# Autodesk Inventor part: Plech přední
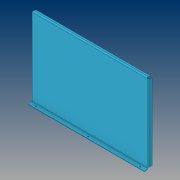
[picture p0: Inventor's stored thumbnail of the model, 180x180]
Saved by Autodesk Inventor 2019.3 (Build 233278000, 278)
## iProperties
Created: 2019-02
Part Number: Plech přední
Material: Ocel, měkká, svařovaná
Document SubType Name: Plech
Designer: B-hon
Density: 7.85 g/cm^3
Sheet Metal Rule: Výchozí_mm
Appearance: Tyrkysová
Flat Pattern Width: 51.832 cm
Flat Pattern Length: 74.7572 cm
Flat Pattern Area: 3874.81 cm^2
Sheet Metal Width: 518,320 mm
Sheet Metal Length: 747,572 mm
Sheet Metal Area: 387481,115 mm^2
Author: B-hon
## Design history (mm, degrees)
node "Plocha1"
  sketch "Náčrt1"
    geometry: L1 (-354, 235)-(354, 235); L2 (354, 235)-(354, -235); L3 (354, -235)-(-354, -235); L4 (-354, -235)-(-354, 235); L5 (-354, 235)-(354, -235); L6 (354, 235)-(-354, -235); 1 further point
    constraints: 12 end point, 2 midpoint, 2 parallel, 1 horizontal, 1 perpendicular
    dimensions: "d0" = 708 distance of L2.end L3.end; "d1" = 470 distance of L1.end L2.end
node "Obruba2"
node "Obruba7"
node "Upravit přímo6"
sketch "Náčrt11"
  geometry: L1 (9.039, 11.735)-(-3, 11.735); L2 (-3, 11.735)-(-3, -36.973); L3 (-3, -36.973)-(9.039, -36.973); L4 (9.039, -36.973)-(9.039, 11.735); L5 (-727.872, -54.321)-(-699, -54.321); L6 (-699, -54.321)-(-699, 24.046); L7 (-699, 24.046)-(-727.872, 24.046); L8 (-727.872, 24.046)-(-727.872, -54.321); L9 (-699, -22)-(-699, -25) reference; 3 further points
  constraints: 16 end point, 4 parallel, 2 horizontal, 2 perpendicular, 2 point on line, 1 midpoint
extrude "Vysunutí4" cut sketch "Náčrt11" distance "d129" = 10; taper "d130" = 0 deg
node "Obruba8"
chamfer "Zkosení1" distance "d141" = 18; stored, may be unused: second distance "d142" = 2, angle "d143" = 20 deg
chamfer "Zkosení2" distance "d144" = 18; stored, may be unused: second distance "d145" = 2, angle "d146" = 20 deg
sketch "Náčrt13"
  geometry: L1 (0, 0)-(708, 0) reference; L2 (708, 20.141)-(708, 0) reference; 2 further points
  dimensions: "d147" = 10 distance from line of L1 point (673, 10); "d148" = 35 distance from line of L2 point (673, 10)
hole "Díra1" sketch "Náčrt13" at (673, 10) diameter "d149" = 6.5; stored, may be unused: countersink angle "d153" = 90 deg, drill point angle "d155" = 118 deg; dims "d150" = 20, "d151" = 4, "d152" = 2, "d154" = 3 (= Tloušťka)
pattern_linear "Obdélníkové pole1" dims "d158" = 317
node "Těleso1"
feature "Deska1" dims "d2" = 3 (= Tloušťka)
sketch "Náčrt3"
  geometry: L1 through (-354, 0) direction (1, -2.79e-33); L2 through (0, 12.5) direction (2.09e-17, 1); L3 (0, 25)-(-708, 25); L4 (-708, 25)-(-708, 0)
  constraints: 6 end point, 1 horizontal, 1 perpendicular, 1 vertical
feature "Deska3" dims "d2" = 3 (= Tloušťka), "d13" = 3 (= ŠířkaVýštipu), "d14" = 1.5 (= HloubkaVýštipu), "d15" = 6 (= MinimálníZbytek), "d16" = 3 (= PřechodovýPoloměr), "d17" = 25, "d18" = 78 deg, "d19" = 3 (= PoloměrOhybu), "d20" = 12 (= VelikostRohovéhoVýštipu), "d21" = 3 (= VelikostMezery), "d22" = 3 (= VelikostJacobihoPoloměru), "MezeraVystřižení" = 0.01
feature "Ohyb2" dims "d2" = 3 (= Tloušťka), "d13" = 3 (= ŠířkaVýštipu), "d14" = 1.5 (= HloubkaVýštipu), "d15" = 6 (= MinimálníZbytek), "d16" = 3 (= PřechodovýPoloměr), "d17" = 25, "d18" = 78 deg, "d19" = 3 (= PoloměrOhybu), "MezeraVystřižení" = 0.01
feature "Roh2" dims "d17" = 25, "d18" = 78 deg, "d20" = 12 (= VelikostRohovéhoVýštipu), "d21" = 3 (= VelikostMezery), "d22" = 3 (= VelikostJacobihoPoloměru)
sketch "Náčrt10"
  geometry: L1 through (232.571, 0) direction (-1, -1.19e-18); L2 through (0, -12.5) direction (0, -1); L3 (0, -25)-(465.141, -25); L4 (465.141, -25)-(465.141, 0)
  constraints: 6 end point, 1 horizontal, 1 perpendicular, 1 vertical
feature "Deska8" dims "d2" = 3 (= Tloušťka), "d113" = 3 (= ŠířkaVýštipu), "d114" = 1.5 (= HloubkaVýštipu), "d115" = 6 (= MinimálníZbytek), "d116" = 3 (= PřechodovýPoloměr), "d117" = 25, "d118" = 90 deg, "d119" = 3 (= PoloměrOhybu), "d120" = 12 (= VelikostRohovéhoVýštipu), "d121" = 3 (= VelikostMezery), "d122" = 3 (= VelikostJacobihoPoloměru), "MezeraVystřižení" = 0.01
feature "Ohyb7" dims "d2" = 3 (= Tloušťka), "d113" = 3 (= ŠířkaVýštipu), "d114" = 1.5 (= HloubkaVýštipu), "d115" = 6 (= MinimálníZbytek), "d116" = 3 (= PřechodovýPoloměr), "d117" = 25, "d118" = 90 deg, "d119" = 3 (= PoloměrOhybu), "MezeraVystřižení" = 0.01
feature "Roh7" dims "d117" = 25, "d118" = 90 deg, "d120" = 12 (= VelikostRohovéhoVýštipu), "d121" = 3 (= VelikostMezery), "d122" = 3 (= VelikostJacobihoPoloměru)
sketch "Náčrt12"
  geometry: L1 through (348, 0) direction (-1, 0); L2 through (0, -12.5) direction (0, -1); L3 (0, -25)-(696, -25); L4 (696, -25)-(696, 0)
  constraints: 6 end point, 1 horizontal, 1 perpendicular, 1 vertical
feature "Deska9" dims "d2" = 3 (= Tloušťka), "d131" = 3 (= ŠířkaVýštipu), "d132" = 1.5 (= HloubkaVýštipu), "d133" = 6 (= MinimálníZbytek), "d134" = 3 (= PřechodovýPoloměr), "d135" = 25, "d136" = 110 deg, "d137" = 3 (= PoloměrOhybu), "d138" = 12 (= VelikostRohovéhoVýštipu), "d139" = 3 (= VelikostMezery), "d140" = 3 (= VelikostJacobihoPoloměru), "MezeraVystřižení" = 0.01
feature "Ohyb8" dims "d2" = 3 (= Tloušťka), "d131" = 3 (= ŠířkaVýštipu), "d132" = 1.5 (= HloubkaVýštipu), "d133" = 6 (= MinimálníZbytek), "d134" = 3 (= PřechodovýPoloměr), "d135" = 25, "d136" = 110 deg, "d137" = 3 (= PoloměrOhybu), "MezeraVystřižení" = 0.01
feature "Roh8" dims "d135" = 25, "d136" = 110 deg, "d138" = 12 (= VelikostRohovéhoVýštipu), "d139" = 3 (= VelikostMezery), "d140" = 3 (= VelikostJacobihoPoloměru)
feature "Posunout14" dims "d125" = 5.5
feature "Posunout15" dims "d128" = 5.5
feature "Definice1"
other parameters: "Tloušťka" = 3 (derived), "KSoučinitel" = 4.4, "PoloměrOhybu" = 3 (= Tloušťka), "ŠířkaVýštipu" = 3 (= Tloušťka), "HloubkaVýštipu" = 1.5 (= 0.5 x Tloušťka), "VelikostRohovéhoVýštipu" = 12 (= 4 x Tloušťka), "MinimálníZbytek" = 6 (= 2 x Tloušťka), "PřechodovýPoloměr" = 3 (= PoloměrOhybu), "VelikostJacobihoPoloměru" = 3 (= PoloměrOhybu), "VelikostMezery" = 3 (= Tloušťka), "d123" = 0, "d124" = 0, "d126" = 0, "d127" = 0, "HloubkaVýštipu" = 1.5, "MinimálníZbytek" = 6, "PoloměrOhybu" = 3, "PřechodovýPoloměr" = 3, "Tloušťka" = 3, "VelikostJacobihoPoloměru" = 3, "VelikostMezery" = 3, "VelikostRohovéhoVýštipu" = 12, "ŠířkaVýštipu" = 3
